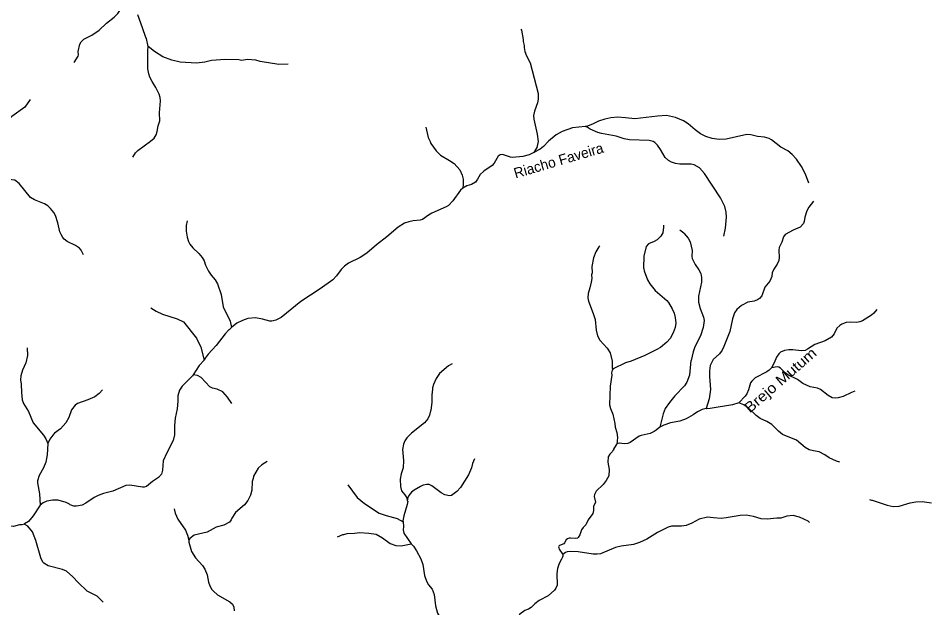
# Model space of a CAD drawing. Extents: x 280.4 to 335.6, y 8893.9 to 8949.5.
# Drawn here: x 295.78 to 309.86, y 8914.46 to 8923.61 of the extents above; entities that cross this region are included whole.
import ezdxf
from ezdxf.enums import TextEntityAlignment as Align

# ---------------------------------------------------------------- set-up
doc = ezdxf.new("R2010")
doc.units = 0
doc.header["$LTSCALE"] = 0.064
doc.layers.add('61', color=7, linetype='Continuous')
doc.layers.add('7', color=7, linetype='Continuous', lineweight=25)

msp = doc.modelspace()

# ---------------------------------------------------------------- linework, layer by layer
at = {"layer": '7'}
for points in [[(296.6498, 8922.9222), (296.7088, 8923.0187), (296.7132, 8923.0372), (296.7103, 8923.0909), (296.7327, 8923.2034), (296.7552, 8923.2417), (296.7954, 8923.2814), (296.9212, 8923.3423), (297.0378, 8923.4207), (297.1509, 8923.5303), (297.2681, 8923.6219), (297.3237, 8923.6789), (297.3585, 8923.7255), (297.3848, 8923.7754), (297.4006, 8923.8241)], [(297.7973, 8923.1706), (297.7696, 8923.2947), (297.7589, 8923.3091), (297.7076, 8923.4581), (297.6381, 8923.66)], [(303.5858, 8923.4369), (303.5938, 8923.4211), (303.6237, 8923.2758), (303.6239, 8923.2458), (303.638, 8923.1862), (303.6365, 8923.151), (303.6492, 8923.091), (303.6763, 8923.0238), (303.7308, 8922.9175), (303.8555, 8922.4377), (303.8554, 8922.3505), (303.8463, 8922.293), (303.7964, 8922.1633), (303.782, 8922.0987), (303.7882, 8922.0393), (303.8398, 8921.8068), (303.8538, 8921.6924), (303.8346, 8921.6005), (303.7901, 8921.526)], [(297.5561, 8921.4502), (297.5992, 8921.5172), (297.6355, 8921.5535), (297.8337, 8921.6972), (297.8895, 8921.7487), (297.9222, 8921.7979), (297.9379, 8921.8512), (297.9511, 8921.9394), (297.98, 8922.0155), (297.9718, 8922.1413), (297.9862, 8922.3264), (297.9844, 8922.3783), (297.9699, 8922.4295), (297.9178, 8922.5306), (297.857, 8922.6265), (297.8228, 8922.695), (297.8054, 8922.7463), (297.7912, 8922.8222), (297.7912, 8923.1046), (297.7973, 8923.1706)], [(299.9706, 8922.8931), (299.8271, 8922.888), (299.5363, 8922.9377), (299.4711, 8922.9554), (299.3406, 8922.966), (299.2448, 8922.953), (299.2041, 8922.9597), (298.9945, 8922.966), (298.7809, 8922.9499), (298.6771, 8922.9247), (298.5499, 8922.9119), (298.2932, 8922.9247), (298.1646, 8922.9553), (298.0271, 8923.0096), (297.895, 8923.0909), (297.7973, 8923.1706)], [(295.9657, 8922.3463), (295.8814, 8922.229), (295.6801, 8922.0834), (295.6262, 8922.0359), (295.5845, 8921.988), (295.5693, 8921.9583), (295.5506, 8921.8787), (295.5233, 8921.6739), (295.504, 8921.6075), (295.4819, 8921.5658), (295.437, 8921.5092), (295.2344, 8921.3128), (295.1716, 8921.2278), (295.1151, 8921.1129)], [(308.0621, 8921.05), (308.0071, 8921.1878), (307.9452, 8921.3051), (307.8675, 8921.4185), (307.8034, 8921.4938), (307.7321, 8921.5492), (307.625, 8921.6047), (307.48, 8921.7214), (307.4417, 8921.7423), (307.3706, 8921.7635), (307.2634, 8921.7702), (307.1595, 8921.7971), (307.0968, 8921.802), (306.7755, 8921.7287), (306.6678, 8921.7267), (306.5565, 8921.7406), (306.4588, 8921.7735), (306.3782, 8921.816), (306.2958, 8921.8744), (306.1855, 8921.9687), (306.112, 8922.013), (305.9873, 8922.0663), (305.8481, 8922.0961), (305.7091, 8922.09), (305.3573, 8922.0452), (305.2131, 8922.0644), (305.0908, 8922.0707), (304.9853, 8922.0611), (304.8886, 8922.0418), (304.7926, 8922.0114), (304.6974, 8921.9654), (304.6054, 8921.9298), (304.5839, 8921.9274)], [(302.1081, 8921.9191), (302.1462, 8921.7565), (302.1797, 8921.6925), (302.189, 8921.6619), (302.2705, 8921.5477), (302.3391, 8921.4827), (302.479, 8921.4001), (302.5489, 8921.3509), (302.6395, 8921.2569), (302.6746, 8921.1702), (302.6877, 8921.1126), (302.6913, 8921.0312), (302.6856, 8920.9685)], [(304.5839, 8921.9274), (304.3897, 8921.9058), (304.2297, 8921.8499), (304.1337, 8921.7971), (304.0133, 8921.7022), (303.9389, 8921.6153), (303.887, 8921.5742), (303.7901, 8921.526)], [(306.7384, 8920.2272), (306.7629, 8920.3473), (306.7789, 8920.5186), (306.7773, 8920.5961), (306.7565, 8920.6856), (306.6874, 8920.821), (306.4383, 8921.199), (306.3615, 8921.2853), (306.2775, 8921.3323), (306.2345, 8921.3413), (306.056, 8921.3414), (305.9904, 8921.3507), (305.927, 8921.3726), (305.8799, 8921.3982), (305.8282, 8921.4488), (305.7555, 8921.5722), (305.7094, 8921.6351), (305.6663, 8921.6782), (305.6403, 8921.6936), (305.5795, 8921.7089), (305.2742, 8921.7221), (305.1914, 8921.7367), (305.0677, 8921.7763), (304.8397, 8921.8175), (304.7805, 8921.8354), (304.6641, 8921.887), (304.615, 8921.9185), (304.5839, 8921.9274)], [(303.7901, 8921.526), (303.714, 8921.4882), (303.6188, 8921.4628), (303.4588, 8921.4469), (303.4262, 8921.452), (303.2996, 8921.493), (303.265, 8921.489), (303.2356, 8921.4678), (303.172, 8921.3588), (303.1414, 8921.3201), (303.0093, 8921.2351), (302.9542, 8921.182), (302.9139, 8921.1085), (302.8803, 8921.0636), (302.8198, 8921.0282), (302.7481, 8921.005), (302.6856, 8920.9685)], [(296.7912, 8919.935), (296.7578, 8920.0107), (296.7325, 8920.0397), (296.6662, 8920.0831), (296.5405, 8920.1452), (296.4903, 8920.1797), (296.4693, 8920.2039), (296.4464, 8920.2526), (296.4264, 8920.2953), (296.3935, 8920.4323), (296.3548, 8920.5481), (296.3317, 8920.5909), (296.2809, 8920.6573), (296.2404, 8920.6941), (296.1886, 8920.7288), (296.0294, 8920.7878), (295.9702, 8920.8259), (295.7952, 8921.0438), (295.7265, 8921.0952), (295.5411, 8921.1149), (295.4171, 8921.1399), (295.3538, 8921.143), (295.1173, 8921.1136), (295.1151, 8921.1129)], [(302.6856, 8920.9685), (302.6486, 8920.9389), (302.5286, 8920.7727), (302.4619, 8920.7028), (302.4273, 8920.6802), (302.2056, 8920.5845), (302.1501, 8920.554), (302.0561, 8920.4834), (302.021, 8920.4727), (301.9123, 8920.4643), (301.8461, 8920.4503), (301.7765, 8920.4249), (301.6796, 8920.3673), (301.5019, 8920.2159), (301.3425, 8920.0934), (301.1927, 8919.9612), (301.088, 8919.8969), (300.91, 8919.8044), (300.8447, 8919.7601), (300.7946, 8919.7069), (300.7246, 8919.6096), (300.6641, 8919.5498), (300.4706, 8919.4078), (300.167, 8919.2123), (299.8631, 8918.9629), (299.778, 8918.9203), (299.7198, 8918.9041), (299.6883, 8918.9046), (299.5751, 8918.9362), (299.465, 8918.9564), (299.3456, 8918.9456), (299.2599, 8918.9187), (299.1735, 8918.8755), (299.0903, 8918.8093)], [(308.1324, 8920.7695), (308.0619, 8920.6766), (308.0302, 8920.6166), (307.9978, 8920.5193), (307.9883, 8920.4531), (307.9769, 8920.4213), (307.927, 8920.3652), (307.8169, 8920.3209), (307.6922, 8920.2489), (307.667, 8920.214), (307.6423, 8920.1318), (307.5991, 8920.0493), (307.5946, 8920.01), (307.6009, 8919.8949), (307.5922, 8919.8459), (307.5676, 8919.7906), (307.5147, 8919.7149), (307.4916, 8919.6587), (307.4867, 8919.6023), (307.4556, 8919.5252), (307.3776, 8919.4362), (307.3286, 8919.3018), (307.2945, 8919.2598), (307.2601, 8919.2358), (307.2107, 8919.2192), (307.1098, 8919.1992), (307.0131, 8919.1491), (306.9421, 8919.0895), (306.9061, 8919.0336), (306.8765, 8918.9449), (306.8319, 8918.7448), (306.7402, 8918.5132), (306.7112, 8918.4556), (306.6711, 8918.4017), (306.5723, 8918.3101), (306.5297, 8918.2202), (306.5167, 8918.1339), (306.5166, 8918.0475), (306.5322, 8917.8439), (306.5121, 8917.703), (306.4632, 8917.5526)], [(298.405, 8920.4658), (298.3895, 8920.3921), (298.3862, 8920.3019), (298.4022, 8920.2084), (298.424, 8920.1408), (298.445, 8920.1014), (298.4883, 8920.0463), (298.5859, 8919.9547), (298.6347, 8919.8936), (298.6646, 8919.8403), (298.6873, 8919.7757), (298.7334, 8919.6807), (298.7743, 8919.6199), (298.837, 8919.5469), (298.8732, 8919.4875), (298.9298, 8919.3223), (298.9637, 8919.1305), (299.0731, 8918.9088), (299.0903, 8918.8093)], [(305.8007, 8920.3985), (305.8029, 8920.3676), (305.7893, 8920.2776), (305.7613, 8920.2277), (305.7038, 8920.1684), (305.6568, 8920.1406), (305.5673, 8920.107), (305.5347, 8920.0666), (305.4964, 8919.9141), (305.4902, 8919.7332), (305.4993, 8919.7165), (305.4997, 8919.6901), (305.5524, 8919.5502), (305.5924, 8919.4837), (305.6752, 8919.3825), (305.8545, 8919.2255), (305.8799, 8919.1937), (305.9377, 8919.0958), (305.9665, 8919.0288), (305.986, 8918.9632), (305.9922, 8918.8759), (305.9855, 8918.8082), (305.9544, 8918.7232), (305.9041, 8918.6355), (305.8524, 8918.579), (305.7541, 8918.5002), (305.701, 8918.4675), (305.5122, 8918.3723), (305.3007, 8918.2877), (305.211, 8918.2592), (305.018, 8918.1667)], [(306.0574, 8920.3226), (306.1185, 8920.2784), (306.1223, 8920.266), (306.184, 8920.1962), (306.2141, 8920.1393), (306.2452, 8920.0007), (306.2416, 8919.9091), (306.2498, 8919.8786), (306.2954, 8919.7863), (306.3506, 8919.7047), (306.3807, 8919.6445), (306.3951, 8919.5846), (306.3951, 8919.5101), (306.3457, 8919.2968), (306.3472, 8919.2016), (306.3729, 8919.1022), (306.4241, 8918.9689), (306.4351, 8918.9165), (306.4168, 8918.8091), (306.3764, 8918.6783), (306.2912, 8918.5106), (306.2606, 8918.4316), (306.232, 8918.2979), (306.226, 8918.2939), (306.2064, 8918.0675), (306.1639, 8917.9601), (306.1271, 8917.9051), (305.9794, 8917.7462), (305.8964, 8917.6469), (305.8297, 8917.5522), (305.7951, 8917.4681), (305.7462, 8917.2621)], [(304.8114, 8920.0749), (304.7977, 8920.0606), (304.7522, 8919.9804), (304.7158, 8919.8886), (304.6888, 8919.7563), (304.6918, 8919.659), (304.6842, 8919.627), (304.6871, 8919.5693), (304.6808, 8919.5093), (304.6604, 8919.4238), (304.6297, 8919.3358), (304.6273, 8919.2689), (304.6369, 8919.2147), (304.7117, 8919.0241), (304.7412, 8918.9303), (304.7544, 8918.769), (304.7782, 8918.6783), (304.8139, 8918.6093), (304.9286, 8918.4866), (304.9717, 8918.4147), (305.0069, 8918.286), (305.004, 8918.1741), (305.018, 8918.1667)], [(297.8393, 8919.115), (297.9234, 8919.0636), (298.0208, 8919.0147), (298.2457, 8918.9438), (298.346, 8918.8942), (298.5482, 8918.6435), (298.6161, 8918.5017), (298.6661, 8918.3025)], [(309.1188, 8919.0857), (309.0685, 8919.0299), (309.0319, 8918.9993), (308.8937, 8918.9119), (308.8521, 8918.8963), (308.7998, 8918.8881), (308.7013, 8918.8912), (308.6401, 8918.8837), (308.5727, 8918.8604), (308.543, 8918.8417), (308.4952, 8918.7964), (308.4525, 8918.7075), (308.4128, 8918.6559), (308.3149, 8918.6037), (308.155, 8918.5445), (308.04, 8918.4699), (308.0055, 8918.4537), (307.9393, 8918.4467), (307.8137, 8918.4625), (307.7489, 8918.4626), (307.6841, 8918.4498), (307.6202, 8918.4273), (307.5927, 8918.4013), (307.5562, 8918.3502), (307.5196, 8918.2585), (307.4792, 8918.1813)], [(299.0903, 8918.8093), (299.0575, 8918.7741), (299.0501, 8918.7733), (298.9911, 8918.7108), (298.8541, 8918.5277), (298.7283, 8918.3971), (298.68, 8918.3308), (298.669, 8918.3056), (298.6661, 8918.3025)], [(295.9189, 8918.4911), (295.9215, 8918.3738), (295.8976, 8918.2586), (295.8428, 8918.1447), (295.8202, 8918.0604), (295.8161, 8917.9988), (295.8256, 8917.9309), (295.8274, 8917.7991), (295.8371, 8917.6847), (295.8612, 8917.6272), (295.9375, 8917.5031), (296.0128, 8917.3305), (296.1706, 8917.1391), (296.2059, 8917.0816), (296.2377, 8917.0067)], [(298.6661, 8918.3025), (298.5903, 8918.2205), (298.497, 8918.0737)], [(302.5182, 8918.2462), (302.4621, 8918.2141), (302.3242, 8918.094), (302.2708, 8918.018), (302.2276, 8917.9218), (302.2127, 8917.8705), (302.2082, 8917.7857), (302.2031, 8917.7779), (302.2018, 8917.6471), (302.189, 8917.5189), (302.1808, 8917.5139), (302.1697, 8917.4456), (302.1414, 8917.3886), (302.0907, 8917.3283), (301.8884, 8917.1688), (301.8176, 8917.098), (301.7863, 8917.0521), (301.7635, 8917.0002), (301.7494, 8916.9153), (301.7636, 8916.7434), (301.7557, 8916.6283), (301.7251, 8916.5396), (301.7125, 8916.4556), (301.7156, 8916.3396), (301.7301, 8916.2743), (301.7828, 8916.2141), (301.8139, 8916.1634), (301.8194, 8916.1166)], [(307.4792, 8918.1813), (307.4461, 8918.1465), (307.4096, 8918.1191), (307.225, 8918.0284), (307.1724, 8917.9781), (307.1538, 8917.9484), (307.1246, 8917.8428), (307.0944, 8917.7789), (307.0701, 8917.7445), (306.975, 8917.6416)], [(308.7766, 8917.8205), (308.7204, 8917.8005), (308.5928, 8917.7393), (308.5166, 8917.7152), (308.4791, 8917.7111), (308.4217, 8917.7194), (308.3586, 8917.7518), (308.2415, 8917.844), (308.1926, 8917.8645), (308.0783, 8917.8885), (307.9663, 8917.9394), (307.8824, 8918.0004), (307.7328, 8918.0737), (307.69, 8918.1034), (307.6217, 8918.1779), (307.595, 8918.1952), (307.5657, 8918.1987), (307.4792, 8918.1813)], [(298.497, 8918.0737), (298.4864, 8918.057), (298.3256, 8917.8971), (298.2856, 8917.8364), (298.2598, 8917.7494), (298.2598, 8917.6627), (298.2485, 8917.5454)], [(299.0983, 8917.6305), (299.0316, 8917.7256), (298.9565, 8917.8076), (298.8665, 8917.8514), (298.7985, 8917.8688), (298.7573, 8917.8873), (298.6189, 8918.0328), (298.5628, 8918.0646), (298.497, 8918.0737)], [(305.018, 8918.1667), (305.0053, 8918.1457), (304.9968, 8918.1065), (305.0002, 8918.0708), (304.9718, 8917.8958), (304.9654, 8917.6094), (304.9813, 8917.5511), (305.0162, 8917.4654), (305.0486, 8917.3201), (305.0519, 8917.2633), (305.0755, 8917.1775), (305.0859, 8917.0999), (305.0794, 8916.9978)], [(297.0869, 8917.8391), (297.0381, 8917.7864), (296.9684, 8917.73), (296.8577, 8917.6841), (296.6993, 8917.6303), (296.6618, 8917.6033), (296.6069, 8917.5302), (296.5619, 8917.4098), (296.5192, 8917.3283), (296.4337, 8917.2348), (296.3399, 8917.1661), (296.314, 8917.1394), (296.2703, 8917.0761), (296.2377, 8917.0067)], [(306.975, 8917.6416), (306.8764, 8917.6067), (306.5255, 8917.5511), (306.4718, 8917.548), (306.4632, 8917.5526)], [(308.5425, 8916.7173), (308.4875, 8916.7327), (308.3744, 8916.7871), (308.3104, 8916.835), (308.2229, 8916.8803), (308.1312, 8916.8924), (308.067, 8916.911), (308.0055, 8916.9465), (307.8679, 8917.06), (307.6506, 8917.1497), (307.5885, 8917.1975), (307.484, 8917.3025), (307.4087, 8917.3488), (307.3042, 8917.3956), (307.2417, 8917.4451), (307.1227, 8917.5559), (307.0486, 8917.6058), (306.975, 8917.6416)], [(298.2485, 8917.5454), (298.2167, 8917.4014), (298.204, 8917.2884), (298.2068, 8917.1409), (298.1874, 8917.0547), (298.0851, 8916.8631), (298.0299, 8916.7402), (298.018, 8916.5932), (298.0019, 8916.5307), (297.9568, 8916.4823), (297.8647, 8916.4204), (297.7692, 8916.3416), (297.7367, 8916.3294), (297.7079, 8916.3293), (297.5107, 8916.364), (297.4488, 8916.3564), (297.2458, 8916.2695), (297.1027, 8916.2331), (297.0177, 8916.2032), (296.9588, 8916.1721), (296.8277, 8916.0826), (296.7692, 8916.0536), (296.686, 8916.0337), (296.6431, 8916.0341), (296.5849, 8916.0569), (296.5733, 8916.0688), (296.5228, 8916.0925), (296.3965, 8916.1277), (296.3086, 8916.1308), (296.2231, 8916.1146), (296.1669, 8916.0881), (296.1182, 8916.0528)], [(306.4632, 8917.5526), (306.4053, 8917.5345), (306.3305, 8917.5011), (306.2617, 8917.4532), (306.1555, 8917.3915), (306.0545, 8917.3532), (305.9114, 8917.3302), (305.806, 8917.2948), (305.7462, 8917.2621)], [(305.7462, 8917.2621), (305.6868, 8917.2158), (305.6571, 8917.1955), (305.5962, 8917.1612), (305.4531, 8917.1324), (305.4221, 8917.1205), (305.2861, 8917.0244), (305.2477, 8917.0062), (305.1912, 8917.0011), (305.1167, 8917.0109), (305.0925, 8917.0077), (305.0794, 8916.9978)], [(296.2377, 8917.0067), (296.227, 8916.8322), (296.2063, 8916.717), (296.1701, 8916.6314), (296.1042, 8916.5121), (296.0768, 8916.4277), (296.0771, 8916.3981), (296.1085, 8916.2285), (296.1182, 8916.0528)], [(305.0794, 8916.9978), (305.0662, 8916.9879), (305.0278, 8916.9212), (305.0255, 8916.9064), (305.0155, 8916.9003), (305.0036, 8916.8764), (304.9702, 8916.8426), (304.942, 8916.8016), (304.9398, 8916.7202), (304.9589, 8916.6043), (304.9524, 8916.5091), (304.911, 8916.4318), (304.8624, 8916.3703), (304.7575, 8916.2684), (304.7289, 8916.2164), (304.7256, 8916.187), (304.7446, 8916.1003), (304.7148, 8916.0302), (304.7123, 8915.9667), (304.7026, 8915.9195), (304.6312, 8915.8239), (304.5979, 8915.7482), (304.5526, 8915.7031), (304.5308, 8915.6675), (304.5024, 8915.5921), (304.4759, 8915.5476), (304.4638, 8915.539), (304.4344, 8915.533), (304.3597, 8915.5384), (304.3347, 8915.5383), (304.3105, 8915.53), (304.2899, 8915.512), (304.2662, 8915.4676), (304.2535, 8915.4515), (304.1882, 8915.4256), (304.1753, 8915.4153), (304.1724, 8915.4025), (304.1738, 8915.3873), (304.1801, 8915.3705), (304.2378, 8915.284)], [(302.8648, 8916.7714), (302.8338, 8916.6977), (302.8173, 8916.6325), (302.7708, 8916.5206), (302.6476, 8916.3255), (302.5925, 8916.2609), (302.5089, 8916.2031), (302.4783, 8916.1966), (302.404, 8916.2123), (302.3469, 8916.2417), (302.205, 8916.35), (302.16, 8916.3722), (302.1258, 8916.3739), (302.0676, 8916.3611), (302.0248, 8916.343), (301.9271, 8916.2847), (301.8853, 8916.2508), (301.8472, 8916.2003), (301.8368, 8916.1745), (301.8294, 8916.1719), (301.8194, 8916.1166)], [(299.6453, 8916.7309), (299.5609, 8916.6786), (299.5063, 8916.6259), (299.4353, 8916.4992), (299.43, 8916.4639), (299.4128, 8916.4195), (299.4061, 8916.2853), (299.3868, 8916.2071), (299.3443, 8916.122), (299.2937, 8916.0583), (299.1521, 8915.9358), (299.0982, 8915.85), (299.0867, 8915.8214), (299.0609, 8915.7877), (298.974, 8915.7433), (298.8556, 8915.7116), (298.7154, 8915.6304), (298.5133, 8915.5868), (298.4419, 8915.5317), (298.4282, 8915.5086)], [(300.8989, 8916.3665), (301.0421, 8916.1716), (301.1549, 8916.0774), (301.3834, 8915.929), (301.4925, 8915.8904), (301.6636, 8915.846), (301.7565, 8915.7951)], [(301.8194, 8916.1166), (301.8287, 8916.1125), (301.8212, 8916.0621), (301.7659, 8915.8843), (301.7548, 8915.8096), (301.7565, 8915.7951)], [(309.004, 8916.1409), (309.0309, 8916.1274), (309.0424, 8916.1289), (309.2761, 8916.0497), (309.3691, 8916.032), (309.4632, 8916.0369), (309.6352, 8916.0877), (309.72, 8916.102), (309.8183, 8916.1068), (309.9654, 8916.0877)], [(296.1182, 8916.0528), (296.1173, 8916.0521), (296.0127, 8915.8847), (295.9371, 8915.7982), (295.8762, 8915.7599), (295.8725, 8915.7589)], [(298.1988, 8915.9924), (298.2152, 8915.9288), (298.257, 8915.8355), (298.3745, 8915.6646), (298.4086, 8915.5864), (298.4282, 8915.5086)], [(301.7565, 8915.7951), (301.7651, 8915.7219), (301.759, 8915.6678), (301.7704, 8915.6147), (301.8848, 8915.449)], [(308.0728, 8915.7842), (308.0475, 8915.8028), (307.9145, 8915.8657), (307.8145, 8915.8894), (307.7194, 8915.8797), (307.624, 8915.8497), (307.565, 8915.851), (307.4122, 8915.8351), (307.3197, 8915.8376), (307.2025, 8915.8731), (307.0853, 8915.8942), (306.9907, 8915.8911), (306.7748, 8915.853), (306.6957, 8915.8463), (306.5806, 8915.8527), (306.4847, 8915.8654), (306.3568, 8915.835), (306.2432, 8915.7712), (306.1558, 8915.7378), (306.0799, 8915.728), (305.9256, 8915.7247), (305.8724, 8915.7114), (305.7095, 8915.6297), (305.5438, 8915.5262), (305.4313, 8915.4707), (305.3379, 8915.4413), (305.1421, 8915.4177), (305.0565, 8915.3958), (304.8246, 8915.2962), (304.7714, 8915.2899), (304.7103, 8915.2913), (304.4777, 8915.3283), (304.364, 8915.3345), (304.3049, 8915.3274), (304.2779, 8915.3153), (304.2378, 8915.284)], [(295.8725, 8915.7589), (295.8336, 8915.7487), (295.7984, 8915.747), (295.7031, 8915.7217), (295.5208, 8915.7344), (295.4459, 8915.7212), (295.2905, 8915.6323), (295.1341, 8915.5521), (295.003, 8915.4428), (294.9079, 8915.3873), (294.8455, 8915.3694), (294.7853, 8915.3666), (294.71, 8915.3848)], [(297.0977, 8914.5444), (297.0052, 8914.6375), (296.8467, 8914.718), (296.7071, 8914.8497), (296.6274, 8914.9406), (296.526, 8915.0274), (296.4663, 8915.0532), (296.2445, 8915.1102), (296.1779, 8915.1501), (296.1623, 8915.1662), (296.1289, 8915.2336), (296.0509, 8915.5015), (295.9999, 8915.6351), (295.9259, 8915.7267), (295.8725, 8915.7589)], [(298.4282, 8915.5086), (298.4264, 8915.4795), (298.4721, 8915.332), (298.5302, 8915.2351), (298.6398, 8915.1158), (298.6767, 8915.0569), (298.7143, 8914.9684), (298.7363, 8914.8548), (298.7555, 8914.7972), (298.7881, 8914.741), (298.8112, 8914.7144), (298.8749, 8914.6617), (299.0673, 8914.5524), (299.1055, 8914.5172), (299.1279, 8914.4677), (299.1312, 8914.4109)], [(300.7371, 8915.5621), (300.8216, 8915.5985), (300.8366, 8915.5958), (300.8904, 8915.6128), (300.9999, 8915.6145), (301.0872, 8915.6256), (301.2256, 8915.6192), (301.3388, 8915.5997), (301.4384, 8915.5444), (301.5577, 8915.4568), (301.6447, 8915.4258), (301.7293, 8915.4222), (301.8848, 8915.449)], [(301.8848, 8915.449), (301.8864, 8915.4467), (301.9188, 8915.4138), (301.9677, 8915.3402), (302.0339, 8915.2193), (302.0645, 8915.1323), (302.0918, 8914.9596), (302.1185, 8914.8746), (302.1539, 8914.8139), (302.2065, 8914.7466), (302.2397, 8914.6644), (302.2609, 8914.4908), (302.2931, 8914.375), (302.3407, 8914.2893), (302.4311, 8914.1622), (302.4639, 8914.075), (302.4702, 8914.0389), (302.4566, 8913.937)], [(304.2378, 8915.284), (304.2404, 8915.2598), (304.235, 8915.2421), (304.2196, 8915.2124), (304.1802, 8915.1458), (304.1564, 8915.0698), (304.1434, 8914.9922), (304.1481, 8914.8107), (304.131, 8914.766)], [(304.131, 8914.766), (304.1084, 8914.7319), (304.0128, 8914.6425), (303.8708, 8914.5712), (303.8022, 8914.5216), (303.7453, 8914.4656), (303.7067, 8914.4391), (303.647, 8914.4145), (303.5691, 8914.3586), (303.5316, 8914.284), (303.4874, 8914.1623)]]:
    msp.add_lwpolyline(points, dxfattribs=at)

# ---------------------------------------------------------------- texts
at = {"layer": '61'}
msp.add_text('Riacho Faveira', height=0.16, rotation=16.39, dxfattribs=at).set_placement((304.1945, 8921.3231), align=Align.CENTER)
at = {"layer": '61', "width": 1.15}
msp.add_text('Brejo Mutum', height=0.16, rotation=41.03, dxfattribs=at).set_placement((307.6703, 8917.9304), align=Align.CENTER)

doc.saveas('drawing.dxf')
